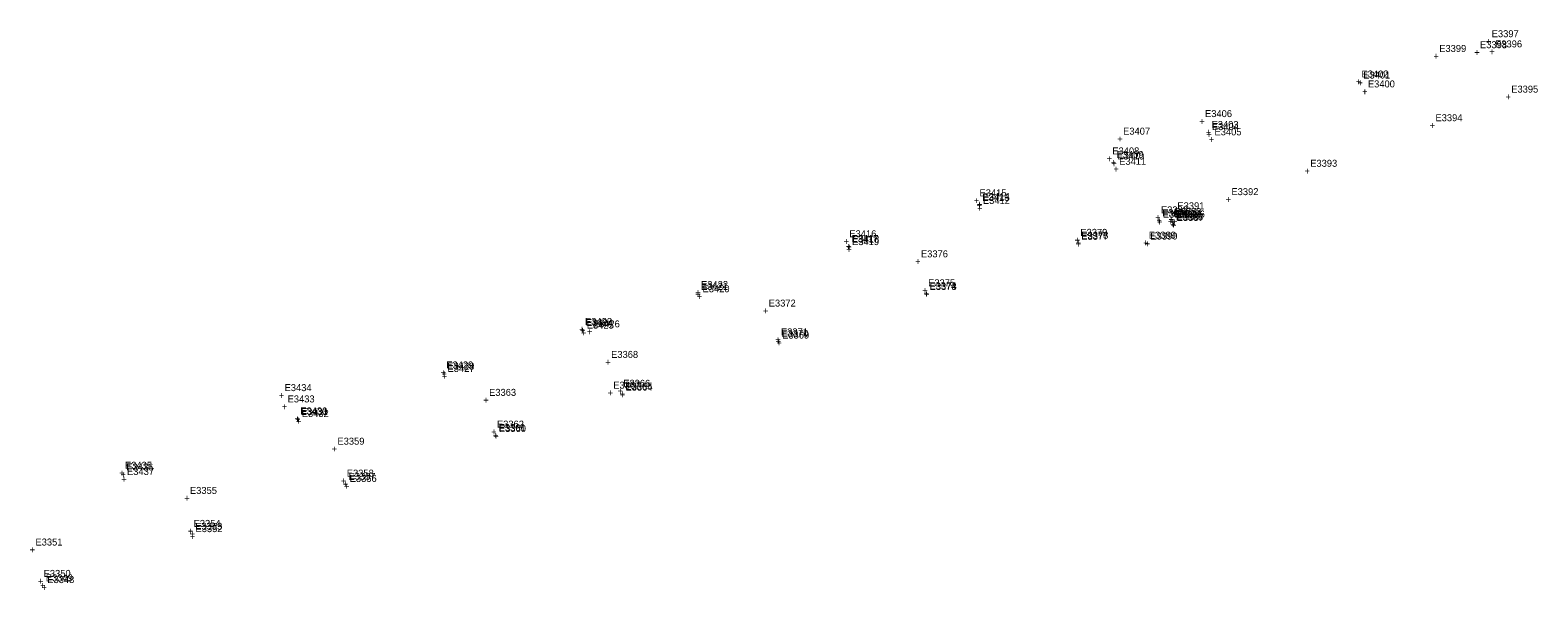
# Model space of a CAD drawing. Extents: x 1667192 to 1669644, y 336680 to 339991.
# Drawn here: x 1669104 to 1669644, y 339791 to 339991 of the extents above; entities that cross this region are included whole.
import ezdxf

# ---------------------------------------------------------------- set-up
doc = ezdxf.new("R2010")
doc.units = 0
for name, color, linetype in [('S_Curb_Type_1', 7, 'Continuous'), ('S_Curb_Type_5', 7, 'Continuous'), ('S_Drainage_CB', 7, 'Continuous'), ('S_Guardrail_Beam', 7, 'Continuous'), ('S_Roadway_Edge_Pavement', 7, 'Continuous'), ('S_Roadway_Edge_TW', 7, 'Continuous'), ('S_Traffic_Sign_DoublePost', 7, 'Continuous'), ('S_Traffic_Sign_SinglePost', 7, 'Continuous'), ('S_Utilities_Pole_StreetLight', 7, 'Continuous')]:
    doc.layers.add(name, color=color, linetype=linetype)

msp = doc.modelspace()

# ---------------------------------------------------------------- texts
at = {"layer": 'S_Curb_Type_1'}
for s, p in [('E3402', (1669580.9, 339974.49)), ('+', (1669578.84, 339971.74)), ('E3403', (1669527.24, 339956.39)), ('+', (1669525.18, 339953.64)), ('E3409', (1669493.24, 339945.64)), ('+', (1669491.18, 339942.89)), ('E3414', (1669445.36, 339930.61)), ('+', (1669443.3, 339927.86)), ('E3417', (1669398.39, 339915.52)), ('+', (1669396.32, 339912.77)), ('E3422', (1669344.54, 339899.06)), ('+', (1669342.48, 339896.31)), ('E3423', (1669303.03, 339885.84)), ('+', (1669300.97, 339883.09)), ('E3429', (1669253.39, 339870.27)), ('+', (1669251.32, 339867.52)), ('E3430', (1669201.13, 339853.78)), ('+', (1669199.07, 339851.03)), ('E3435', (1669138.41, 339834.32)), ('+', (1669136.34, 339831.57))]:
    msp.add_text(s, height=2.5, dxfattribs=at).set_placement(p)
at = {"layer": 'S_Curb_Type_5'}
for s, p in [('E3380', (1669509.78, 339924.24)), ('E3384', (1669513.69, 339924.54)), ('E3385', (1669514.47, 339924.07)), ('+', (1669507.72, 339921.49)), ('+', (1669511.63, 339921.79)), ('+', (1669512.41, 339921.32)), ('+', (1669512.47, 339920.59)), ('E3388', (1669514.54, 339923.34)), ('+', (1669478.57, 339913.58)), ('E3377', (1669480.63, 339916.33)), ('+', (1669502.73, 339914.01)), ('E3389', (1669504.8, 339916.76)), ('E3373', (1669426.35, 339898.37)), ('+', (1669424.29, 339895.62)), ('E3369', (1669373.57, 339880.96)), ('+', (1669371.51, 339878.21)), ('+', (1669315.45, 339859.57)), ('E3364', (1669317.51, 339862.32)), ('+', (1669270.16, 339844.75)), ('E3360', (1669272.22, 339847.5)), ('+', (1669216.74, 339826.85)), ('E3356', (1669218.81, 339829.6)), ('E3352', (1669163.63, 339811.62)), ('+', (1669161.57, 339808.87)), ('+', (1669108.52, 339790.61)), ('E3348', (1669110.58, 339793.36))]:
    msp.add_text(s, height=2.5, dxfattribs=at).set_placement(p)
at = {"layer": 'S_Drainage_CB'}
for s, p in [('E3398', (1669623.3, 339984.98)), ('+', (1669621.24, 339982.23)), ('+', (1669303.75, 339882.21)), ('E3426', (1669305.81, 339884.96)), ('+', (1669311.08, 339860.27)), ('E3367', (1669313.14, 339863.02))]:
    msp.add_text(s, height=2.5, dxfattribs=at).set_placement(p)
at = {"layer": 'S_Guardrail_Beam'}
for s, p in [('E3399', (1669608.71, 339983.64)), ('+', (1669606.64, 339980.89)), ('E3408', (1669491.73, 339946.93)), ('+', (1669489.67, 339944.18)), ('E3415', (1669444.2, 339931.9)), ('+', (1669442.14, 339929.15)), ('+', (1669395.56, 339914.51)), ('E3416', (1669397.62, 339917.26))]:
    msp.add_text(s, height=2.5, dxfattribs=at).set_placement(p)
at = {"layer": 'S_Roadway_Edge_Pavement'}
for s, p in [('E3397', (1669627.5, 339988.92)), ('+', (1669625.44, 339986.17)), ('E3401', (1669581.53, 339974.11)), ('+', (1669579.47, 339971.36)), ('+', (1669525.32, 339952.88)), ('E3404', (1669527.38, 339955.63)), ('E3410', (1669493.44, 339945.11)), ('+', (1669491.37, 339942.36)), ('E3413', (1669445.21, 339930.29)), ('+', (1669443.15, 339927.54)), ('E3381', (1669509.58, 339924.72)), ('E3383', (1669513.92, 339925.16)), ('E3386', (1669515.18, 339924.36)), ('+', (1669507.52, 339921.97)), ('+', (1669511.86, 339922.41)), ('+', (1669512.71, 339920.34)), ('+', (1669513.12, 339921.61)), ('E3387', (1669514.77, 339923.09)), ('E3418', (1669398.66, 339915.31)), ('+', (1669478.57, 339913.96)), ('E3378', (1669480.63, 339916.71)), ('+', (1669503.27, 339913.69)), ('E3390', (1669505.34, 339916.44)), ('+', (1669396.6, 339912.56)), ('E3421', (1669344.55, 339898.4)), ('E3374', (1669426.28, 339898.56)), ('+', (1669342.49, 339895.65)), ('+', (1669424.22, 339895.81)), ('+', (1669301.23, 339882.67)), ('E3424', (1669303.3, 339885.42)), ('E3370', (1669373.31, 339881.54)), ('+', (1669371.25, 339878.79)), ('E3428', (1669253.72, 339869.83)), ('+', (1669251.66, 339867.08)), ('+', (1669315.37, 339859.91)), ('E3365', (1669317.43, 339862.66)), ('E3431', (1669201.34, 339853.53)), ('+', (1669199.28, 339850.78)), ('+', (1669270.06, 339845.05)), ('E3361', (1669272.12, 339847.8)), ('E3436', (1669138.85, 339833.71)), ('+', (1669136.79, 339830.96)), ('+', (1669216.33, 339827.6)), ('E3357', (1669218.4, 339830.35)), ('E3353', (1669163.55, 339812.44)), ('+', (1669161.49, 339809.69)), ('+', (1669108.02, 339791.25)), ('E3349', (1669110.08, 339794))]:
    msp.add_text(s, height=2.5, dxfattribs=at).set_placement(p)
at = {"layer": 'S_Roadway_Edge_TW'}
for s, p in [('E3396', (1669628.71, 339985.26)), ('+', (1669626.65, 339982.51)), ('+', (1669581.12, 339968.18)), ('E3400', (1669583.18, 339970.93)), ('E3395', (1669634.48, 339969.07)), ('+', (1669632.42, 339966.32)), ('E3394', (1669607.37, 339958.82)), ('+', (1669526.24, 339951.02)), ('E3405', (1669528.3, 339953.77)), ('+', (1669605.31, 339956.07)), ('+', (1669492.12, 339940.46)), ('E3411', (1669494.18, 339943.21)), ('E3393', (1669562.55, 339942.5)), ('+', (1669560.49, 339939.75)), ('E3412', (1669445.41, 339929.19)), ('+', (1669532.29, 339929.59)), ('E3392', (1669534.35, 339932.34)), ('+', (1669443.34, 339926.44)), ('E3382', (1669509.12, 339925.83)), ('+', (1669512.96, 339924.52)), ('E3391', (1669515.02, 339927.27)), ('+', (1669507.06, 339923.08)), ('E3419', (1669398.59, 339914.44)), ('+', (1669478.23, 339915.01)), ('E3379', (1669480.29, 339917.76)), ('+', (1669396.53, 339911.69)), ('E3376', (1669423.24, 339910.06)), ('+', (1669421.17, 339907.31)), ('E3420', (1669345.08, 339897.55)), ('E3375', (1669425.81, 339899.7)), ('+', (1669343.02, 339894.8)), ('E3372', (1669368.77, 339892.42)), ('+', (1669423.75, 339896.95)), ('+', (1669366.7, 339889.67)), ('+', (1669301.6, 339881.78)), ('E3425', (1669303.66, 339884.53)), ('E3371', (1669373.15, 339882.1)), ('+', (1669371.08, 339879.35)), ('+', (1669310.31, 339871.28)), ('E3368', (1669312.37, 339874.03)), ('+', (1669251.76, 339866.27)), ('E3427', (1669253.82, 339869.02)), ('E3363', (1669268.7, 339860.44)), ('+', (1669314.65, 339860.94)), ('E3366', (1669316.71, 339863.69)), ('+', (1669266.64, 339857.69)), ('+', (1669199.6, 339850.11)), ('E3432', (1669201.66, 339852.86)), ('E3362', (1669271.5, 339849.07)), ('E3359', (1669214.43, 339842.94)), ('+', (1669269.44, 339846.32)), ('+', (1669212.36, 339840.19)), ('E3437', (1669139.13, 339832.09)), ('+', (1669137.07, 339829.34)), ('+', (1669215.71, 339828.75)), ('E3358', (1669217.77, 339831.5)), ('+', (1669159.59, 339822.56)), ('E3355', (1669161.65, 339825.31)), ('+', (1669160.89, 339810.75)), ('E3354', (1669162.95, 339813.49)), ('E3351', (1669106.36, 339806.82)), ('+', (1669104.3, 339804.07)), ('E3350', (1669109.29, 339795.58)), ('+', (1669107.23, 339792.83))]:
    msp.add_text(s, height=2.5, dxfattribs=at).set_placement(p)
at = {"layer": 'S_Traffic_Sign_DoublePost'}
for s, p in [('+', (1669193.45, 339859.38)), ('E3434', (1669195.51, 339862.13)), ('+', (1669194.53, 339855.33)), ('E3433', (1669196.59, 339858.08))]:
    msp.add_text(s, height=2.5, dxfattribs=at).set_placement(p)
at = {"layer": 'S_Traffic_Sign_SinglePost'}
for s, p in [('+', (1669522.84, 339957.55)), ('E3406', (1669524.9, 339960.3))]:
    msp.add_text(s, height=2.5, dxfattribs=at).set_placement(p)
at = {"layer": 'S_Utilities_Pole_StreetLight'}
for s, p in [('+', (1669493.52, 339951.25)), ('E3407', (1669495.58, 339954))]:
    msp.add_text(s, height=2.5, dxfattribs=at).set_placement(p)

doc.saveas('drawing.dxf')
